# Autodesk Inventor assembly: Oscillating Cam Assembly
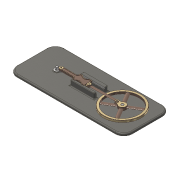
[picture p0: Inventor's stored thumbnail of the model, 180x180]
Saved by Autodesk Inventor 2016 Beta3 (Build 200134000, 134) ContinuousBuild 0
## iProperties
Created: 2016-03
Part Number: Oscillating Cam Assembly
Document SubType Name: Assembly
Designer: Gaurav
Author: Gaurav
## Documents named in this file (10)
- D:\My Data\Books_Final Books\Autodesk Inventor 2015_resources\Chapter 7\oscillating-cam-mechanism\Oscillating Cam Assembly.iam
- D:\My Data\Books_Final Books\Autodesk Inventor 2015_resources\Chapter 7\oscillating-cam-mechanism\Base Plate.ipt
- D:\My Data\Books_Final Books\Autodesk Inventor 2015_resources\Chapter 7\oscillating-cam-mechanism\Oscillating Wheel.ipt
- D:\My Data\Books_Final Books\Autodesk Inventor 2015_resources\Chapter 7\oscillating-cam-mechanism\Lever.ipt
- D:\My Data\Books_Final Books\Autodesk Inventor 2015_resources\Chapter 7\oscillating-cam-mechanism\Tappet.ipt
- D:\My Data\Books_Final Books\Autodesk Inventor 2015_resources\Chapter 7\oscillating-cam-mechanism\Bearing.ipt
- D:\My Data\Books_Final Books\Autodesk Inventor 2015_resources\Chapter 7\oscillating-cam-mechanism\Shaft 5x8.ipt
- D:\My Data\Books_Final Books\Autodesk Inventor 2015_resources\Chapter 7\oscillating-cam-mechanism\Pin 5x13.ipt
- D:\My Data\Books_Final Books\Autodesk Inventor 2015_resources\Chapter 7\oscillating-cam-mechanism\Pin 5x22.ipt
- D:\My Data\Books_Final Books\Autodesk Inventor 2015_resources\Chapter 7\oscillating-cam-mechanism\Pin 12x26.ipt
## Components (10 placed, 9 different names)
1. Base Plate:1 — Insert:1, Mate:1, Insert:9
2. Oscillating Wheel:1 — Insert:1, Insert:2, Insert:8
3. Lever:1 — Insert:2, Insert:3, Insert:7
4. Tappet:1 — Insert:3, Mate:1, Insert:4, Insert:5, Insert:6
5. Bearing:1 — Insert:4
6. Shaft 5x8:1 — Insert:5
7. Pin 5x13:1 — Insert:6
8. Pin 5x22:1 — Insert:7
9. Pin 12x26:1 — Insert:9
10. Pin 12x26:2 — Insert:8
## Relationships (10: Insert 9, Mate 1)
- Insert:1: Base Plate:1 ↔ Oscillating Wheel:1
- Insert:2: Oscillating Wheel:1 ↔ Lever:1
- Insert:3: Lever:1 ↔ Tappet:1
- Mate:1: Base Plate:1 ↔ Tappet:1
- Insert:4: Tappet:1 ↔ Bearing:1
- Insert:5: Tappet:1 ↔ Shaft 5x8:1
- Insert:6: Tappet:1 ↔ Pin 5x13:1
- Insert:7: Lever:1 ↔ Pin 5x22:1
- Insert:8: Oscillating Wheel:1 ↔ Pin 12x26:2
- Insert:9: Base Plate:1 ↔ Pin 12x26:1
